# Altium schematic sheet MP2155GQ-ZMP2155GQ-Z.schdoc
size 127 x 101 mm
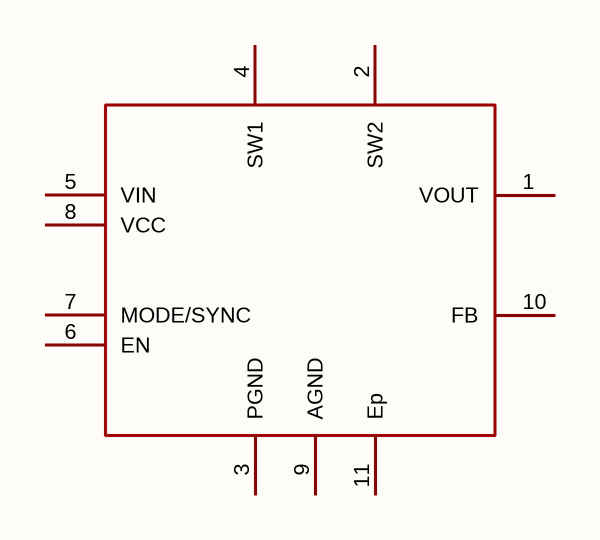
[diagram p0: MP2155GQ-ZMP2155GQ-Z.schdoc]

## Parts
U?  mp2155gq-z  [QFN-10_L3.0-W3.0-P0.50-LS3.0-BL-EP]  (value not drawn)

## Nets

Not connected (* = marked no-connect by the designer): U? 1(VOUT) 2(SW2) 3(PGND) 4(SW1) 5(VIN) 6(EN) 7(MODE/SYNC) 8(VCC) 9(AGND) 10(FB) 11(Ep)

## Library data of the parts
U? = mp2155gq-z: 功能类型:升降压型;工作电压:2V~5.5V;输出电压:1.5V~5V;输出电流:1A;输出类型:可调;; Manufacturer: MPS(芯源); AddInBom: yes; ModelId: 3ccf4f2a47f440b7b94e80bf86aaca96; ModelName: QFN-10_L3.0-W3.0-H1.0-P0.50; ModelTransform: 118.11,117.327,0,90,0,0,0,0,0; Function: 升降压型; Output Current: 1A; Frequency - Switching: 1MHz; Synchronous Rectifier: 否; Number of Outputs: 1; Topology: 降压-升压式; Quiescent Current: 80uA; Switch tube (built-in/external): 内置; Output Type: 可调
